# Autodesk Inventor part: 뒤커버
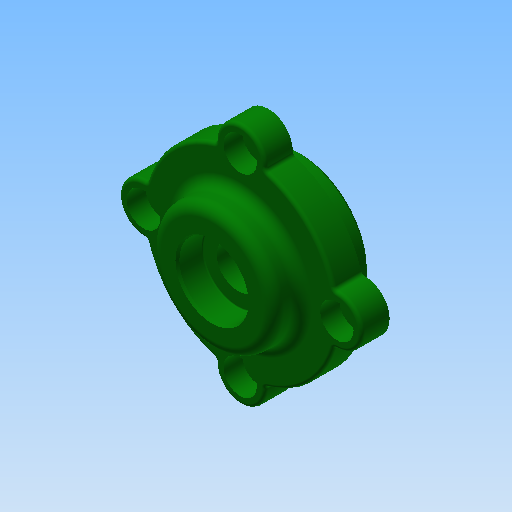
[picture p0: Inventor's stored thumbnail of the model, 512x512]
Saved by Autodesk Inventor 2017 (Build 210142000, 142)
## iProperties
Created: 2016-05
Part Number: 뒤커버
Document SubType Name: Modeling
Designer: mduedu
Density: 2.71 g/cm^3
Material: 알루미늄 6061
Appearance: 진녹색
Author: mduedu
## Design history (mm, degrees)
sketch "스케치1"
  geometry: C1 r 20 at (0, 0); C2 r 27.5 at (0, 0); 1 further point
  constraints: 2 centre point, 2 coincident
  dimensions: "d33" = 55 diameter of C2; "d34" = 40 diameter of C1
extrude "돌출1" new body sketch "스케치1" distance "d0" = 8; taper "d1" = 0 deg
extrude "돌출2" join sketch "스케치1" distance "d2" = 8; taper "d3" = 0 deg; dims "d35" = 9, "d36" = 0
sketch "스케치6"
  geometry: C1 r 17.5 at (0, 0); 2 further points
  constraints: 2 coincident, 1 centre point
  dimensions: "d42" = 35 diameter of C1
extrude "돌출4" join sketch "스케치6" distance "d43" = 8; taper "d44" = 0 deg
sketch "스케치4"
  geometry: L1 (0, -9)-(0, 16); L2 (-15, -9)-(-15, 0); L3 (-15, 0)-(-10, 0); L4 (-10, 0)-(-10, 3); L5 (-10, 3)-(-6, 3); L6 (-6, 3)-(-6, 8.7); L7 (-6, 8.7)-(-10, 8.7); L8 (-10, 8.7)-(-10, 16); L9 (20, -9)-(-20, -9) reference; L10 (17.5, 16)-(-17.5, 16) reference; 1 further point
  constraints: 16 end point, 6 parallel, 3 point on line, 2 midpoint, 2 perpendicular, 1 vertical
  dimensions: "d15" = 30 diameter of L2 L1; "d16" = 20 diameter of L8 L1; "d18" = 9 distance of L2.start L2.end; "d19" = 3 distance of L3.end L4.end; "d20" = 20 diameter of L4 L1; "d21" = 12 diameter of L6 L1; "d45" = 7.3 distance of L7.end L8.end
revolve "회전1" sketch "스케치4" stored, may be unused: angle "d22" = 90 deg
fillet "모깎기2" dims "d23" = 3
fillet "모깎기3" dims "d24" = 0.3
chamfer "모따기2" distance "d46" = 1; stored, may be unused: second distance "d47" = 2, angle "d48" = 45 deg
sketch "스케치7"
  geometry: C1 r 7 at (0, 27.5); 2 further points
  constraints: 3 vertical alignment, 1 centre point, 2 other
  dimensions: "d54" = 14 diameter of C1
extrude "돌출5" join sketch "스케치7" stored distance "d55" = 10; taper "d56" = 0 deg
fillet "모깎기6" dims "d57" = 1
sketch "스케치10"
  geometry: C1 r 17.5 at (0, 0) reference; A1 r 27.5 centre (0, 0) between (26.395, 7.718) and (7.718, 26.395) reference; A2 r 1 centre (7.999, 27.355) between (6.999, 27.373) and (7.718, 26.395) reference; A3 r 7 centre (0, 27.5) between (6.999, 27.373) and (-6.999, 27.373) reference; A4 r 1 centre (-7.999, 27.355) between (-7.718, 26.395) and (-6.999, 27.373) reference; A5 r 27.5 centre (0, 0) between (-7.718, 26.395) and (-26.395, 7.718) reference; A6 r 1 centre (-27.355, 7.999) between (-27.373, 6.999) and (-26.395, 7.718) reference; A7 r 7 centre (-27.5, 0) between (-27.373, 6.999) and (-27.373, -6.999) reference; A8 r 1 centre (-27.355, -7.999) between (-26.395, -7.718) and (-27.373, -6.999) reference; A9 r 27.5 centre (0, 0) between (-26.395, -7.718) and (-7.718, -26.395) reference; A10 r 1 centre (-7.999, -27.355) between (-6.999, -27.373) and (-7.718, -26.395) reference; A11 r 7 centre (0, -27.5) between (-6.999, -27.373) and (6.999, -27.373) reference; A12 r 1 centre (7.999, -27.355) between (7.718, -26.395) and (6.999, -27.373) reference; A13 r 27.5 centre (0, 0) between (7.718, -26.395) and (26.395, -7.718) reference; A14 r 1 centre (27.355, -7.999) between (27.373, -6.999) and (26.395, -7.718) reference; A15 r 7 centre (27.5, 0) between (27.373, -6.999) and (27.373, 6.999) reference; A16 r 1 centre (27.355, 7.999) between (26.395, 7.718) and (27.373, 6.999) reference; 4 further points
  constraints: 3 coincident
hole "구멍3" sketch "스케치10" at (0, 27.5), (-27.5, 0), (0, -27.5), (27.5, 0) diameter "d81" = 5.5; stored, may be unused: countersink angle "d85" = 90 deg, drill point angle "d87" = 118 deg; dims "d82" = 6, "d83" = 9.5, "d84" = 5.4, "d86" = 8
fillet "모깎기7" dims "d61" = 1
fillet "모깎기8" dims "d88" = 3
chamfer "모따기3" distance "d76" = 0.7; stored, may be unused: second distance "d77" = 2, angle "d78" = 30 deg
node "솔리드1"
pattern_circular "원형 패턴1" dims angle "d59" = 360 deg
node "투영된 루프1"
